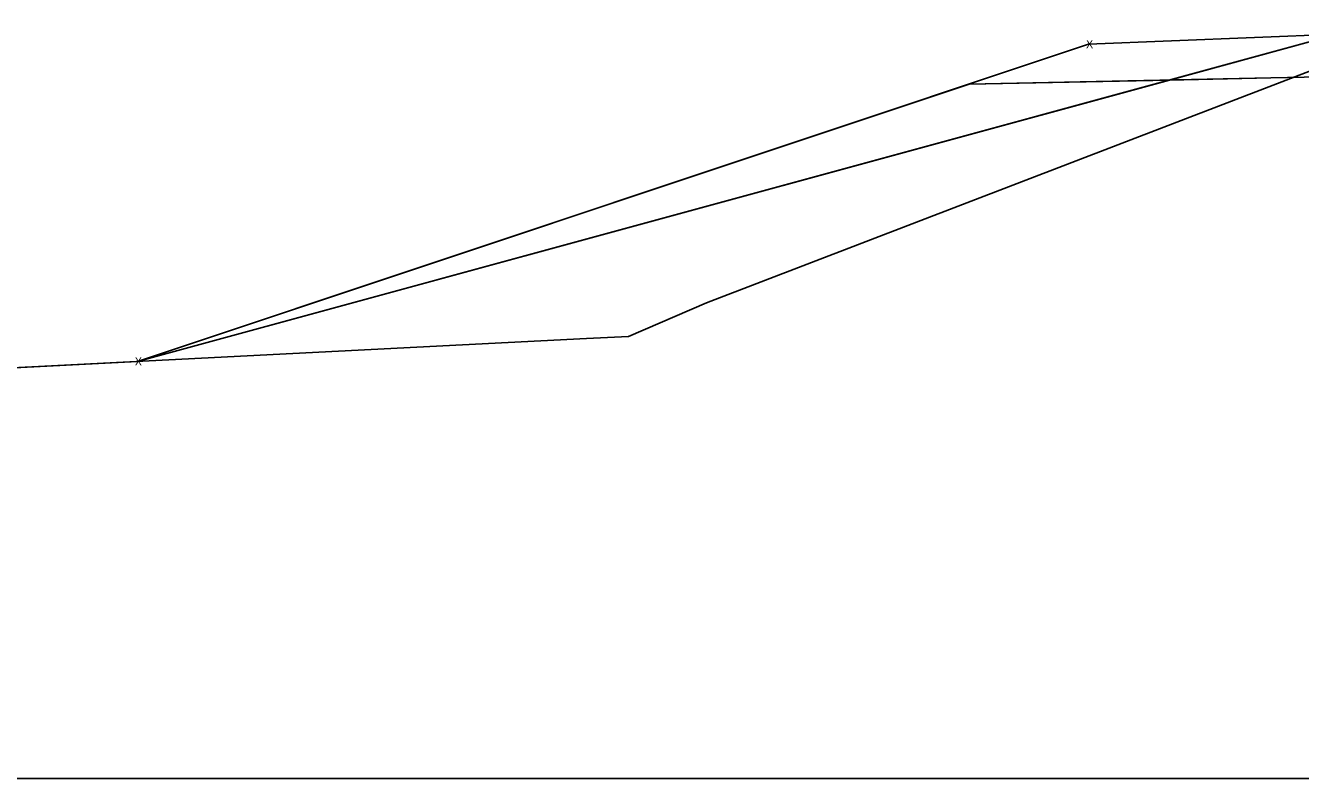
# Model space of a CAD drawing. Extents: x -26 to 303, y -16 to 6048.
# Drawn here: x 97.55 to 135.79, y 3000 to 3022.57 of the extents above; entities that cross this region are included whole.
import ezdxf

# ---------------------------------------------------------------- set-up
doc = ezdxf.new("R2010")
doc.units = 0
for name, color, linetype in [('DTM_P_FINISHED_GRADE2', 7, 'Continuous'), ('DTM_TEMP_DROP', 7, 'Continuous'), ('DTM_X_GROUND', 7, 'Continuous'), ('XS_CELL', 7, 'Continuous'), ('XS_M_SHAPES_EARTHWORK', 7, 'Continuous'), ('XS_P_GROUND', 7, 'Continuous'), ('XS_P_SHOULDER', 7, 'Continuous'), ('XS_P_SUBGRADE_GRANULAR', 7, 'Continuous')]:
    doc.layers.add(name, color=color, linetype=linetype)

msp = doc.modelspace()

# ---------------------------------------------------------------- linework, layer by layer
at = {"layer": 'DTM_P_FINISHED_GRADE2'}
msp.add_lwpolyline([(100.909, 3012.502), (100.909, 3012.502), (129.436, 3022.011), (136.898, 3022.31), (138.898, 3022.35), (150, 3022.572), (161.342, 3022.345), (163.342, 3022.305), (170.335, 3022.025), (196.584, 3013.275), (199.023, 3012.463)], dxfattribs=at)
at = {"layer": 'DTM_X_GROUND'}
for points in [[(90.987, 3011.993), (100.909, 3012.502), (100.909, 3012.502), (136.898, 3022.31), (136.898, 3022.31), (138.898, 3022.35), (138.898, 3022.35), (150, 3022.572), (161.342, 3022.345), (161.342, 3022.345), (163.342, 3022.305), (163.342, 3022.305), (163.342, 3022.305), (196.361, 3013.35), (196.584, 3013.275), (196.704, 3013.235), (199.023, 3012.463), (199.023, 3012.463), (199.023, 3012.463), (199.023, 3012.463), (199.023, 3012.463), (204.279, 3012.279)], [(90.297, 3011.958), (114.375, 3013.193), (115.641, 3013.245), (117.971, 3014.259), (136.605, 3021.412), (136.898, 3021.446), (141.492, 3021.538), (149.994, 3021.716), (159.289, 3021.672), (163.342, 3021.651), (165.342, 3021.457), (167.862, 3021.214), (170.435, 3019.941), (184.541, 3012.969), (186.717, 3012.893), (193.229, 3012.665), (195.696, 3012.579), (204.279, 3012.279)]]:
    msp.add_lwpolyline(points, dxfattribs=at)
at = {"layer": 'XS_CELL'}
msp.add_line((0, 3000), (150, 3000), dxfattribs=at)
at = {"layer": 'XS_M_SHAPES_EARTHWORK'}
for points in [[(131.865, 3020.938), (136.898, 3022.31), (138.898, 3022.35), (150, 3022.572), (161.342, 3022.345), (163.342, 3022.305), (168.401, 3020.933), (165.342, 3020.994), (163.342, 3021.034), (161.342, 3021.074), (161.342, 3021.661), (159.289, 3021.672), (150, 3021.716), (149.994, 3021.716), (141.492, 3021.538), (138.898, 3021.486), (138.898, 3021.079), (136.898, 3021.039), (134.898, 3020.999)], [(100.909, 3012.502), (131.865, 3020.938), (125.857, 3020.818)]]:
    msp.add_lwpolyline(points, close=True, dxfattribs=at)
at = {"layer": 'XS_P_GROUND'}
msp.add_lwpolyline([(100.909, 3012.502), (100.909, 3012.502), (129.436, 3022.011)], dxfattribs=at)
at = {"layer": 'XS_P_SHOULDER'}
msp.add_lwpolyline([(136.898, 3022.31), (129.436, 3022.011)], dxfattribs=at)
at = {"layer": 'XS_P_SUBGRADE_GRANULAR'}
msp.add_lwpolyline([(136.898, 3021.039), (134.898, 3020.999), (125.857, 3020.818)], dxfattribs=at)

# ---------------------------------------------------------------- texts
at = {"layer": 'DTM_TEMP_DROP'}
msp.add_text('X', height=0.24, dxfattribs=at).set_placement((100.83, 3012.382))
at = {"layer": 'XS_P_GROUND'}
msp.add_text('X', height=0.24, dxfattribs=at).set_placement((129.358, 3021.891))
at = {"layer": 'XS_P_SUBGRADE_GRANULAR'}
msp.add_text('X', height=0.24, dxfattribs=at).set_placement((100.83, 3012.382))

doc.saveas('drawing.dxf')
